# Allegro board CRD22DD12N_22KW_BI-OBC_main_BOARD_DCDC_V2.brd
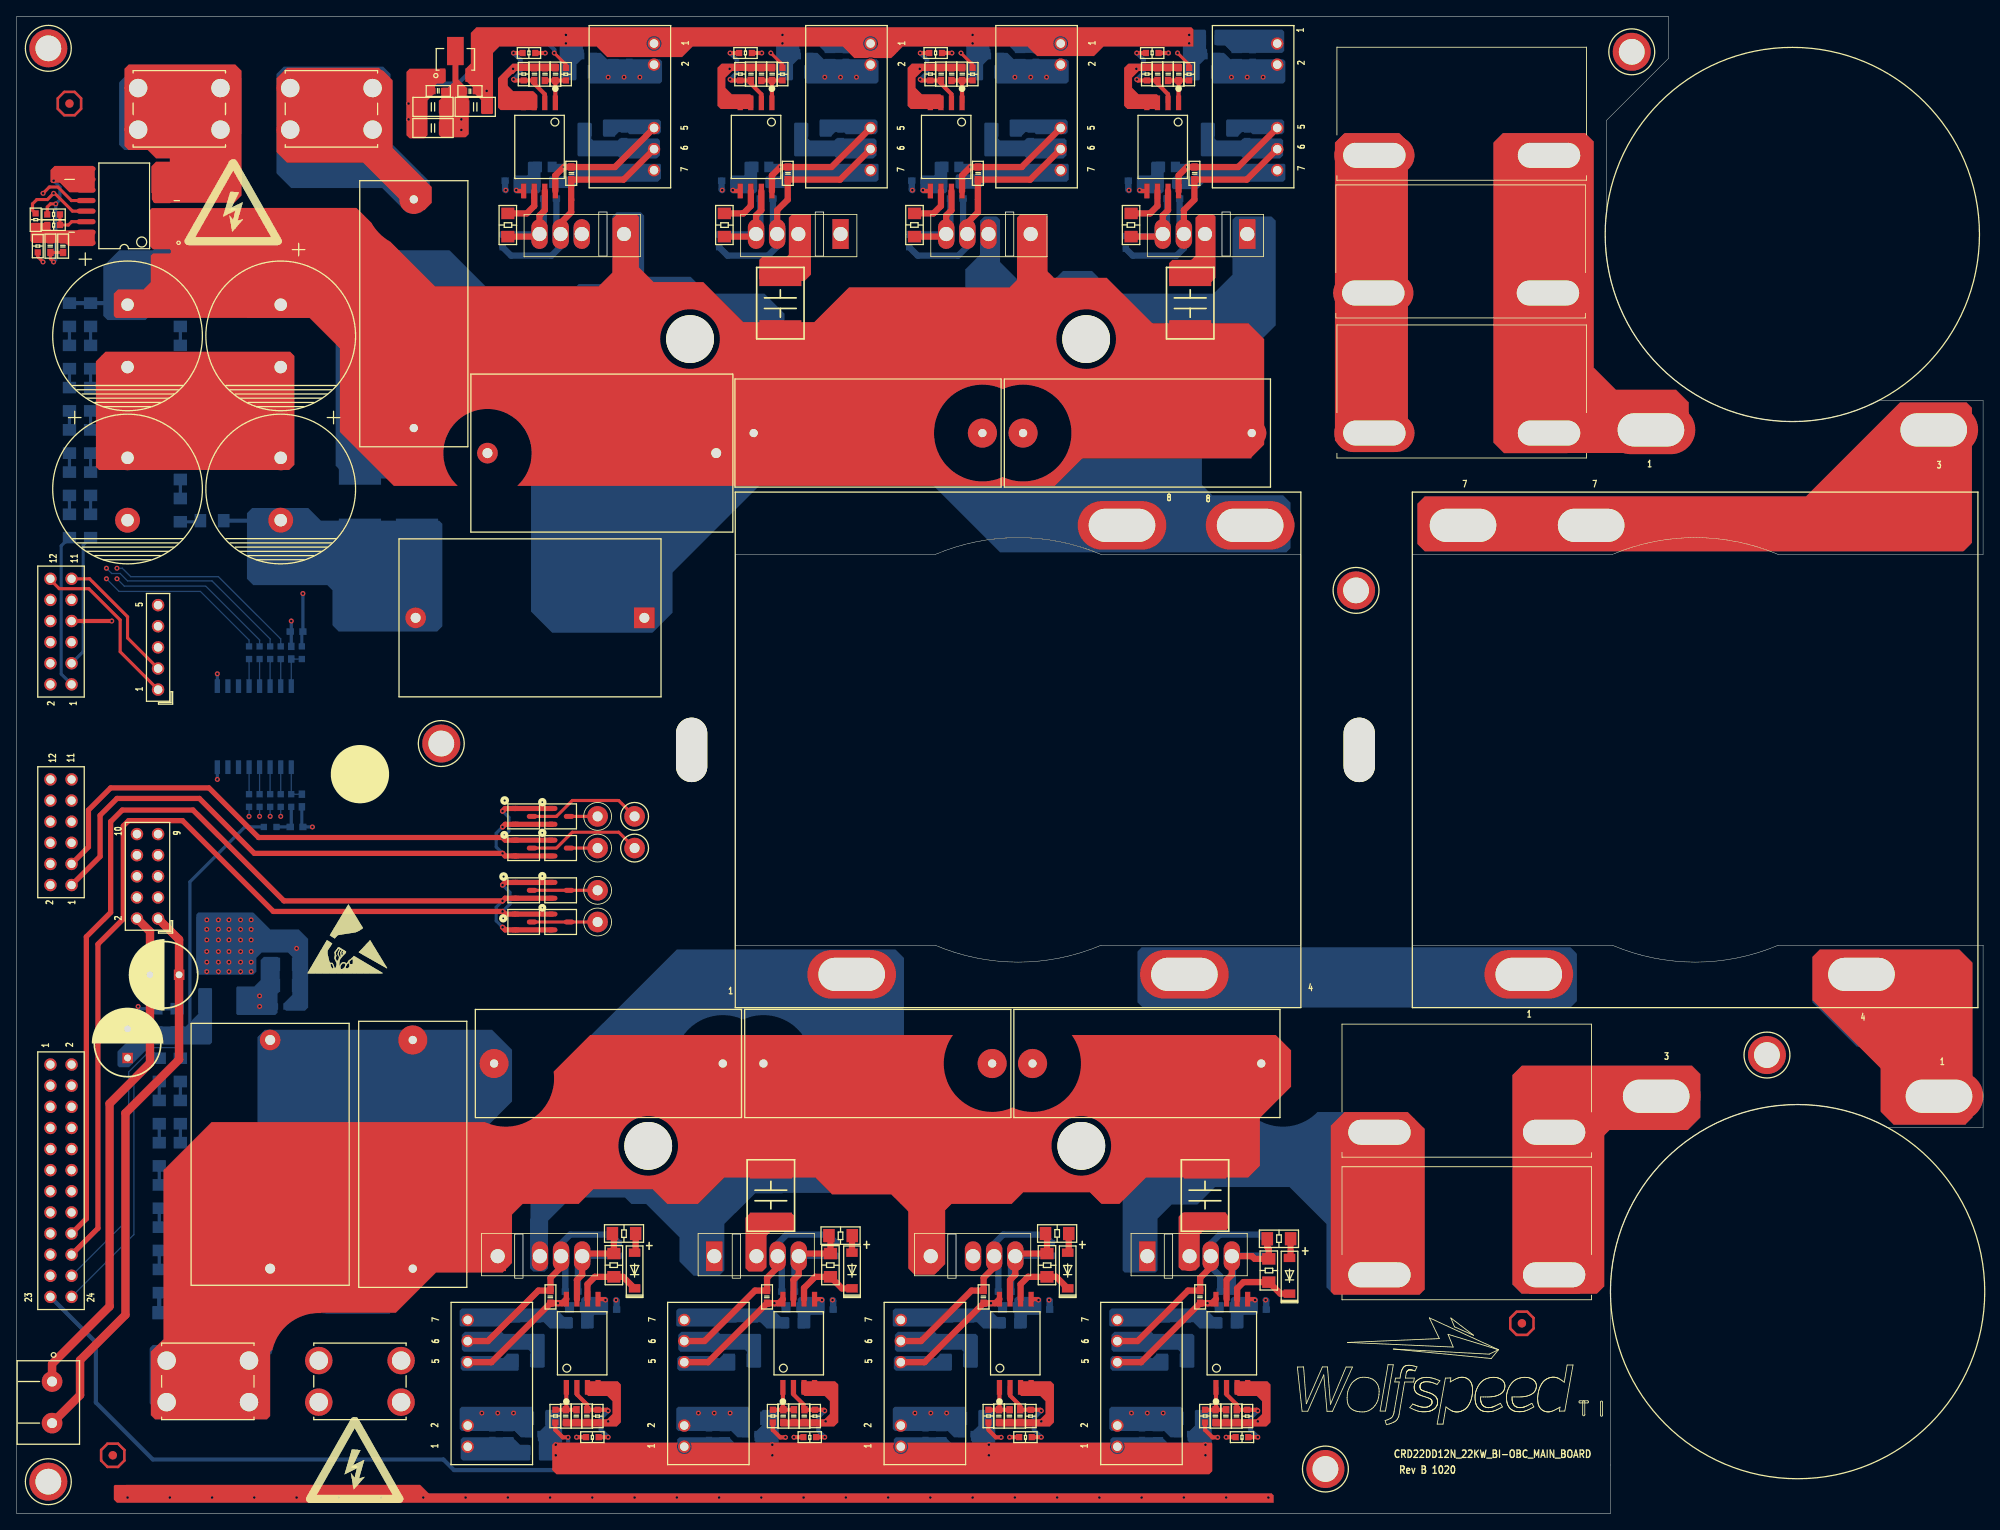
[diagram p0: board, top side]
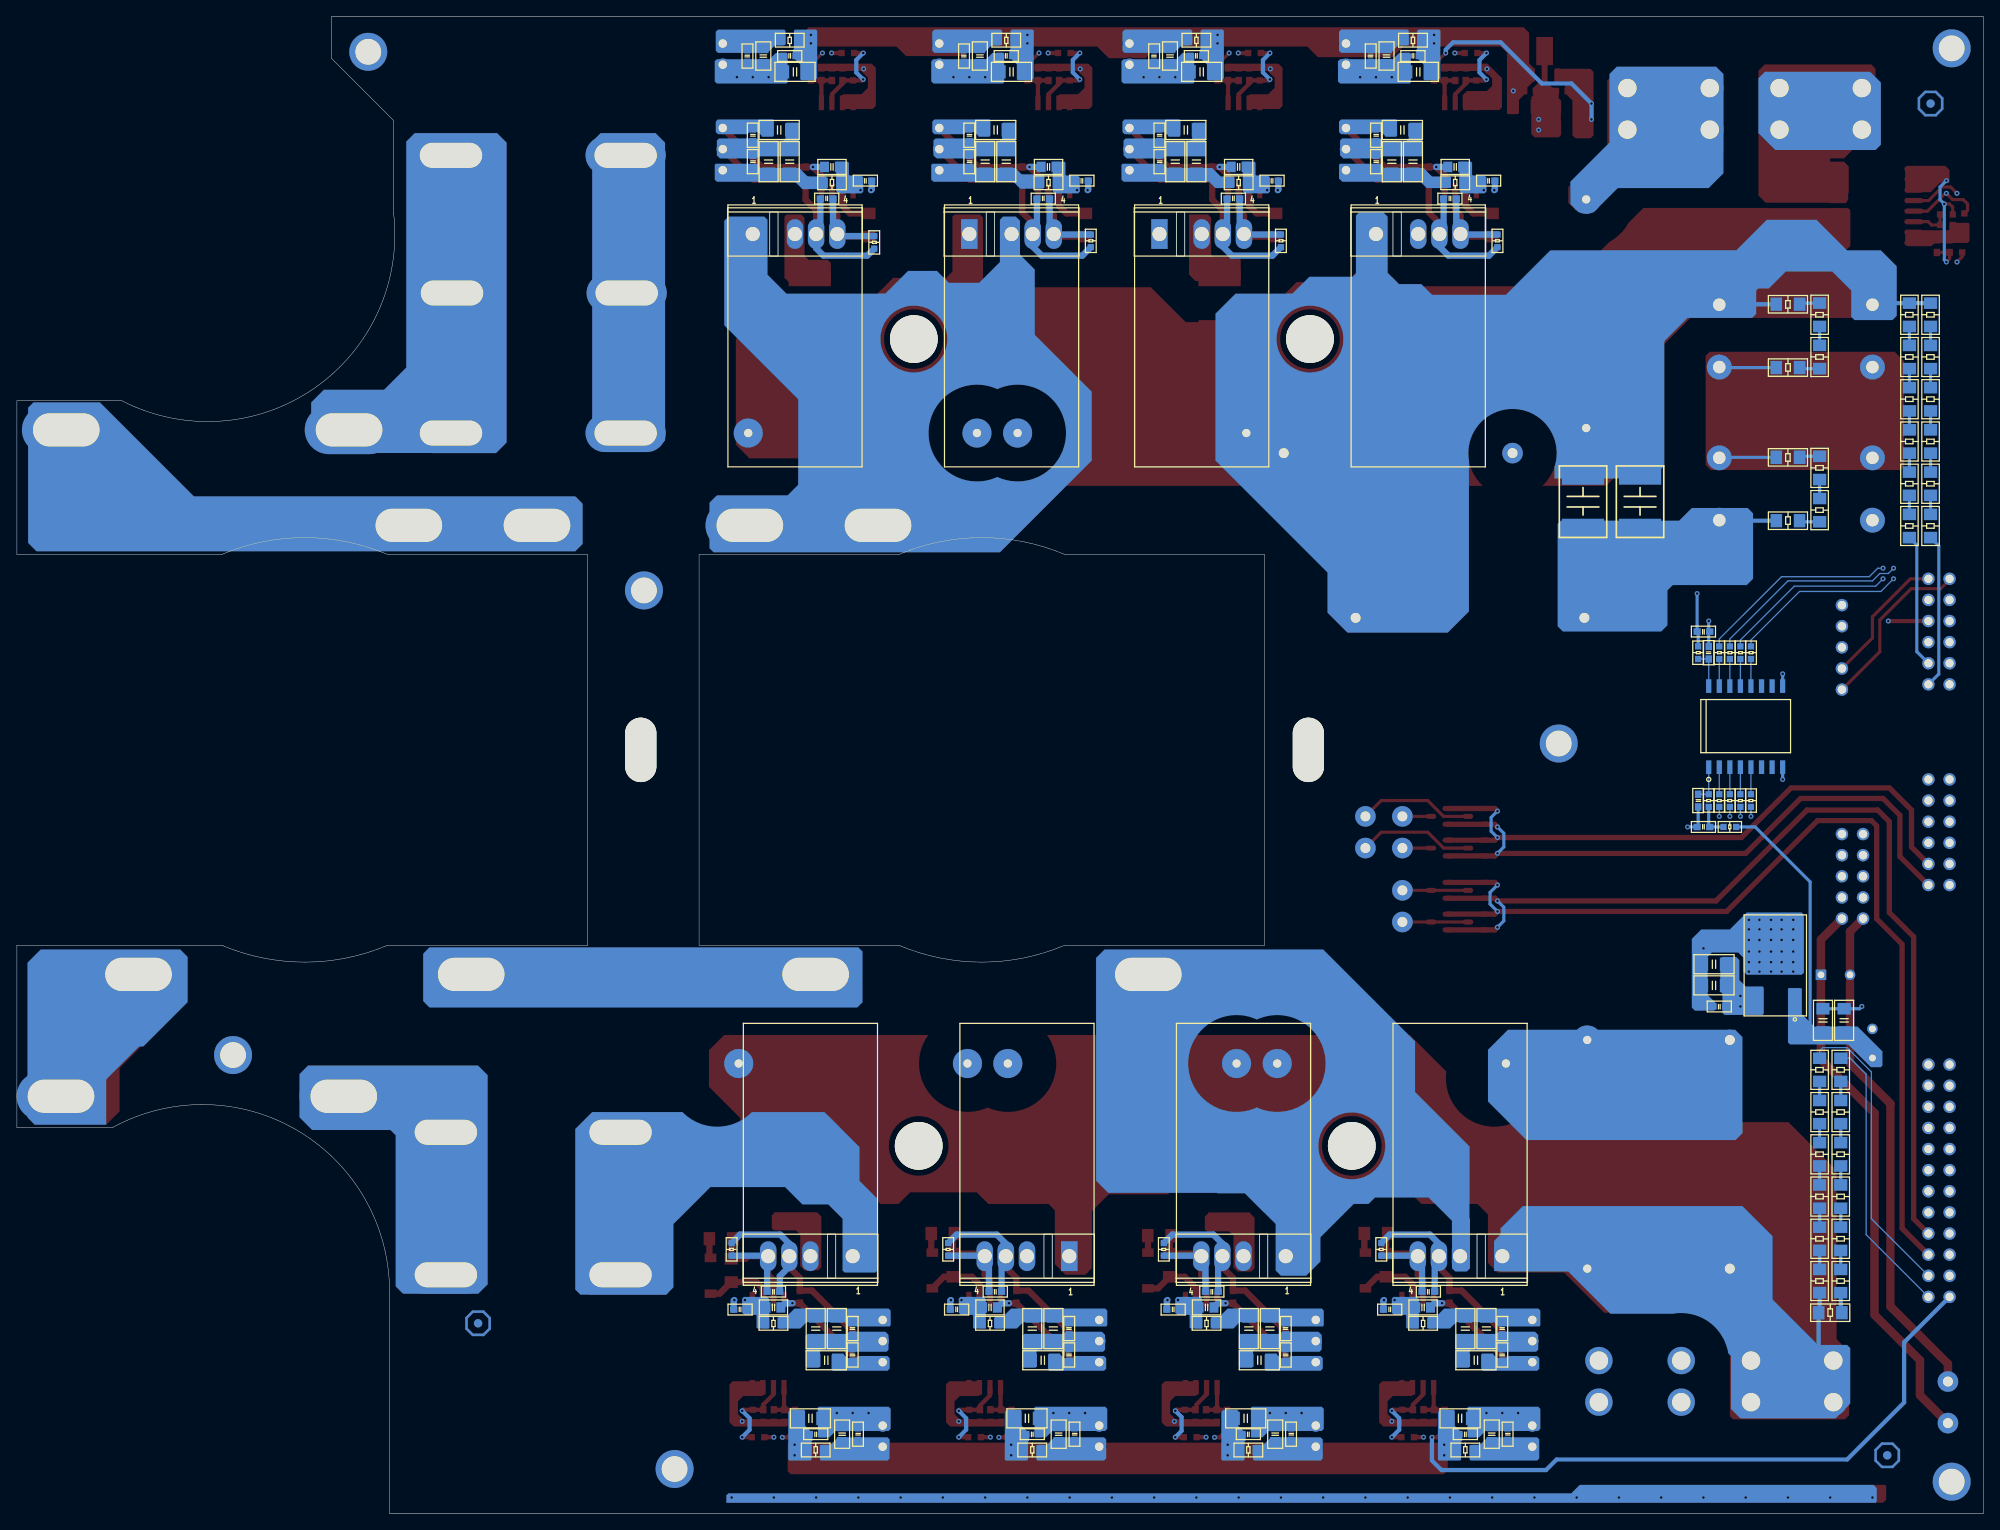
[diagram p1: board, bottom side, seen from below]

Outline 236.43 x 180 mm; copper layers: TOP, GND02, POWER03, BOTTOM. Coordinates in mm from the lower left corner of the outline.
Outline path: rectangle 59.88,28.28 60.88,33.58 ; rectangle 70.98,156.51 69.99,151.21 ; rectangle 86.04,28.28 87.04,33.58 ; rectangle 97.02,156.51 96.02,151.21 ; rectangle 111.95,28.28 112.95,33.58 ; rectangle 119.88,156.51 118.88,151.21 ; rectangle 137.98,28.28 138.98,33.58 ; rectangle 145.91,156.51 144.92,151.21 ; 0,180 198.63,180 198.63,175.01 191.13,167.51 191.13,156.38 arc(200.7,135.29) 223.8,133.81 236.43,133.81 236.43,115.32 211.8,115.32 arc(201.82,117.35) 191.84,115.32 167.79,115.32 167.79,68.33 191.84,68.33 arc(201.82,66.29) 211.8,68.33 236.43,68.33 236.43,46.39 224.94,46.39 arc(202.55,45.96) 191.62,26.41 191.62,0 0,0 0,180 ; 86.41,115.32 110.43,115.32 arc(120.41,117.35) 130.39,115.32 154.41,115.32 154.41,68.33 130.39,68.33 arc(120.41,66.29) 110.43,68.33 86.41,68.33 86.41,115.32

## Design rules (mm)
net group BUS_GAO: nets DCINPUT VO+
net group BUS_DI: nets AGND N16148550 PGND SGND SPGND
net group BUS_POWER: nets -3V_PSW5 -3V_PSW6 -3V_PSW7 -3V_PSW8 -3V_PSW9 -3V_PSW10 -3V_PSW11 -3V_PSW12 CAN5V_GND CAN_5V P6.5V VO1+ VO2+ VP+5V VP+15V VP+15V_DCDCA VP+15V_DCDCB VP+15V_DCDCC VP+15V_DCDCD VS+5V VS+15V VS+15V_DCDCA VS+15V_DCDCB VS+15V_DCDCC VS+15V_DCDCD
net group GAO: nets LEGA LEGB N17988090 N17988199 N17988317 N18067595 SLEGB

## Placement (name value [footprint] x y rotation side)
C1  0u1  [C2220]  142.88 38.23 270 top
C2  0u1  [C2220]  90.68 38.23 270 top
C4  1n  [C0603]  118.8 26.67 180 bottom
C5  1n  [C0603]  66.73 26.67 180 bottom
C7  2.2u  [CAPFILM_31_5X12_5MM]  103.53 54.1 0 top
C8  2.2u  [CAPFILM_31_5X12_5MM]  135.89 54.1 180 top
C10  2.2u  [CAPFILM_31_5X12_5MM]  71.15 54.1 180 top
C14  1n  [C0603]  92.76 26.67 180 bottom
C15  1n  [C0603]  145.47 26.67 180 bottom
C20  0.1U  [C0603]  5.59 152.4 270 top
C21  1U  [C0603]  4.06 152.4 270 top
C22  1n  [C0603]  64.14 158.12 0 bottom
C23  1n  [C0603]  113.03 158.12 0 bottom
C25  450V 180uF  [ECAP_D18P7_5]  31.75 141.6 180 top
C26  450V 180uF  [ECAP_D18P7_5]  13.34 141.6 180 top
C27  0u1  [C2220]  48.13 121.67 270 bottom
C28  0u1  [C2220]  41.27 121.67 270 bottom
C32  2.2u  [CAPFILM_31_5X12_5MM]  47.75 144.27 90 top
C33  2.2u  [CAPFILM_31_5X12_5MM]  134.75 129.92 180 top
C34  2.2u  [CAPFILM_31_5X12_5MM]  102.36 129.92 0 top
C35  5u  [CAPFILM_31_5X18_5MM]  70.36 127.51 180 top
C36  0u1  [C2220]  141.1 145.54 90 top
C37  0u1  [C2220]  91.82 145.54 90 top
C39  450V 180uF  [ECAP_D18P7_5]  31.75 123.19 180 top
C40  450V 180uF  [ECAP_D18P7_5]  13.34 123.19 180 top
C42  1n  [C0603]  90.17 158.12 0 bottom
C43  1n  [C0603]  139.06 158.12 0 bottom
C44  10u  [C1206]  55.14 169.14 0 top
C45  1U  [C0603]  54.5 171.05 0 top
C46  1U  [C0603]  50.69 171.05 180 top
C47  22u  [C1206]  50.06 169.14 180 top
C48  22u  [C1206]  50.06 166.6 180 top
C49  10u  [C1206]  32.38 63.5 180 bottom
C50  1U  [C0603]  31.75 60.96 180 bottom
C51  10u  [C1206]  32.38 66.04 180 bottom
C52  10u  [C1206]  19.28 59.29 270 bottom
C53  10u  [C1206]  16.74 59.29 270 bottom
C54  25V 220uF  [ECAP_D8P3_5]  13.34 56.52 90 top
C55  25V 220uF  [ECAP_D8P3_5]  17.78 64.77 180 top
C56  1uF  [C0603]  57.84 22.23 270 bottom
C57  4u7  [C1206]  62.28 22.23 270 bottom
C58  10uF  [C1206]  59.74 22.23 270 bottom
C59  1uF  [C0603]  83.87 22.23 270 bottom
C60  10uF  [C1206]  85.78 22.23 270 bottom
C61  4u7  [C1206]  114.35 22.23 270 bottom
C62  10uF  [C1206]  111.81 22.23 270 bottom
C64  1uF  [C0603]  135.94 22.23 270 bottom
C65  10uF  [C1206]  137.85 22.23 270 bottom
C66  10uF  [C1206]  62.92 11.43 180 bottom
C67  1uF  [C0603]  62.28 9.53 180 bottom
C68  4u7  [C1206]  88.32 22.23 270 bottom
C69  1uF  [C0603]  109.91 22.23 270 bottom
C70  1uF  [C0603]  88.37 9.53 180 bottom
C71  2u2  [C0805]  85.14 9.53 90 bottom
C72  4u7  [C1206]  140.39 22.23 270 bottom
C73  0u1  [C0603]  57.2 9.53 90 bottom
C74  2u2  [C0805]  59.11 9.53 90 bottom
C75  0u1  [C0603]  83.24 9.53 90 bottom
C76  10uF  [C1206]  114.99 11.43 180 bottom
C77  1uF  [C0603]  114.35 9.53 180 bottom
C78  0u1  [C0603]  109.27 9.53 90 bottom
C79  2u2  [C0805]  111.18 9.53 90 bottom
C80  10uF  [C1206]  141.02 11.43 180 bottom
C81  10uF  [C1206]  88.69 11.43 180 bottom
C82  1uF  [C0603]  140.39 9.53 180 bottom
C83  0u1  [C0603]  135.31 9.53 90 bottom
C84  2u2  [C0805]  137.21 9.53 90 bottom
C85  1uF  [C0603]  57.84 19.05 270 bottom
C86  10uF  [C1206]  61.01 18.41 180 bottom
C87  1uF  [C0603]  109.91 19.05 270 bottom
C88  10uF  [C1206]  113.08 18.41 180 bottom
C89  1uF  [C0603]  83.87 19.05 270 bottom
C90  1uF  [C0603]  135.94 19.05 270 bottom
C91  10uF  [C1206]  87.05 18.41 180 bottom
C92  10uF  [C1206]  139.12 18.41 180 bottom
C93  1uF  [C0603]  73.03 162.56 90 bottom
C94  4u7  [C1206]  68.58 162.56 90 bottom
C95  10uF  [C1206]  71.12 162.56 90 bottom
C96  1uF  [C0603]  68.58 175.26 0 bottom
C97  1uF  [C0603]  99.06 162.56 90 bottom
C98  0u1  [C0603]  73.66 175.26 270 bottom
C99  4u7  [C1206]  94.61 162.56 90 bottom
C100  1uF  [C0603]  121.92 162.56 90 bottom
C101  10uF  [C1206]  67.94 173.35 0 bottom
C102  10uF  [C1206]  97.16 162.56 90 bottom
C103  2u2  [C0805]  71.75 175.26 270 bottom
C104  4u7  [C1206]  117.47 162.56 90 bottom
C105  10uF  [C1206]  120.02 162.56 90 bottom
C106  1uF  [C0603]  147.96 162.56 90 bottom
C107  10uF  [C1206]  146.05 162.56 90 bottom
C108  10uF  [C1206]  93.98 173.35 0 bottom
C109  0u1  [C0603]  99.69 175.26 270 bottom
C110  2u2  [C0805]  97.79 175.26 270 bottom
C111  10uF  [C1206]  116.84 173.35 0 bottom
C112  1uF  [C0603]  117.47 175.26 0 bottom
C113  1uF  [C0603]  73.03 165.74 90 bottom
C114  10uF  [C1206]  69.85 166.37 0 bottom
C115  0u1  [C0603]  122.56 175.26 270 bottom
C116  2u2  [C0805]  120.65 175.26 270 bottom
C117  4u7  [C1206]  143.51 162.56 90 bottom
C118  1uF  [C0603]  94.61 175.26 0 bottom
C119  10uF  [C1206]  142.88 173.35 0 bottom
C120  1uF  [C0603]  143.51 175.26 0 bottom
C121  0u1  [C0603]  148.59 175.26 270 bottom
C122  2u2  [C0805]  146.69 175.26 270 bottom
C123  1uF  [C0603]  99.06 165.74 90 bottom
C124  10uF  [C1206]  95.89 166.37 0 bottom
C125  1uF  [C0603]  121.92 165.74 90 bottom
C126  10uF  [C1206]  118.75 166.37 0 bottom
C127  1uF  [C0603]  147.96 165.74 90 bottom
C128  10uF  [C1206]  144.78 166.37 0 bottom
C129  0u1  [C0603]  33.66 106.05 180 bottom
C130  0u1  [C0603]  33.66 82.55 0 bottom
C131  0u1  [C0603]  34.29 85.72 90 bottom
C132  0u1  [C0603]  33.02 103.5 270 bottom
C134  1U  [C0603]  67.31 11.7 270 top
C135  0.1U  [C0603]  66.04 11.7 270 top
C136  1n  [C0603]  68.58 11.7 270 top
C137  2.2u  [C0805]  67.36 24.77 180 bottom
C138  1U  [C0603]  71.37 24.51 0 bottom
C139  1U  [C0603]  64.19 26.04 270 top
C141  1U  [C0603]  92.18 11.7 270 top
C142  0.1U  [C0603]  93.45 11.7 270 top
C143  1n  [C0603]  94.72 11.7 270 top
C144  1U  [C0603]  97.41 24.51 0 bottom
C145  2.2u  [C0805]  93.4 24.77 180 bottom
C146  1U  [C0603]  90.22 26.04 270 top
C148  1U  [C0603]  119.38 11.7 270 top
C149  0.1U  [C0603]  118.11 11.7 270 top
C150  1n  [C0603]  120.65 11.7 270 top
C151  2.2u  [C0805]  119.43 24.77 180 bottom
C152  1U  [C0603]  123.44 24.51 0 bottom
C153  1U  [C0603]  116.26 26.04 270 top
C155  1U  [C0603]  145.41 11.7 270 top
C156  0.1U  [C0603]  144.15 11.7 270 top
C157  1n  [C0603]  146.69 11.7 270 top
C158  1U  [C0603]  149.48 24.51 0 bottom
C159  2.2u  [C0805]  145.47 24.77 180 bottom
C160  1U  [C0603]  142.29 26.04 270 top
C161  1U  [C0603]  63.5 173.08 90 top
C162  0.1U  [C0603]  64.77 173.08 90 top
C163  1n  [C0603]  62.23 173.08 90 top
C164  2.2u  [C0805]  63.5 161.93 0 bottom
C165  1U  [C0603]  59.49 160.27 180 bottom
C166  1U  [C0603]  66.67 161.15 90 top
C167  1U  [C0603]  90.81 173.08 90 top
C168  0.1U  [C0603]  89.53 173.08 90 top
C169  1n  [C0603]  88.27 173.08 90 top
C170  1U  [C0603]  85.52 160.27 180 bottom
C171  2.2u  [C0805]  89.53 161.93 0 bottom
C172  1U  [C0603]  92.71 161.15 90 top
C173  0.1U  [C0603]  113.67 173.08 90 top
C174  1U  [C0603]  112.39 173.08 90 top
C175  1n  [C0603]  111.12 173.08 90 top
C176  2.2u  [C0805]  112.39 161.93 0 bottom
C177  1U  [C0603]  108.38 160.27 180 bottom
C178  1U  [C0603]  115.57 161.15 90 top
C179  1U  [C0603]  138.43 173.08 90 top
C180  0.1U  [C0603]  139.7 173.08 90 top
C181  1n  [C0603]  137.16 173.08 90 top
C182  1U  [C0603]  134.42 160.27 180 bottom
C183  2.2u  [C0805]  138.43 161.93 0 bottom
C184  1U  [C0603]  141.6 161.15 90 top
C185  2.2u  [CAPFILM_31_5X12_5MM]  47.62 43.18 90 top
C186  5u  [CAPFILM_31_5X18_5MM]  61.72 107.7 180 top
C633  5u  [CAPFILM_31_5X18_5MM]  30.48 43.18 90 top
CON1  Connecter  [THREAD4_9P9X5_1110X920]  22.99 15.88 180 top
CON2  Connecter  [THREAD4_9P9X5_1110X920]  41.27 15.88 180 top
CON3  Connecter  [THREAD4_9P9X5_1110X920]  19.56 168.91 180 top
CON4  Connecter  [THREAD4_9P9X5_1110X920]  37.85 168.91 180 top
CR1  3PIN  [CRB]  174.35 45.84 180 top
CR2  3PIN  [CRB]  174.35 28.69 180 top
CR3  3PIN  [CRB]  173.74 163.32 180 top
CR4  3PIN  [CRB]  173.61 146.77 180 top
CR5  3PIN  [CRB]  173.74 129.92 180 top
CT1  T1T2  [TH47_CR98]  69.85 74.93 270 top
CT2  T1T2  [TH47_CR98]  69.85 83.82 270 top
CT5  T1T2  [TH47_CR98]  69.85 71.12 270 top
CT6  T1T2  [TH47_CR98]  69.85 80.01 270 top
CT7  T1T2  [TH47_CR98]  74.3 83.82 0 top
CT8  T1T2  [TH47_CR98]  74.3 80.01 0 top
D1  SL14PL-TP  [SOD-123]  74.3 29.21 270 top
D2  SL14PL-TP  [SOD-123]  126.36 29.21 270 top
D3  BAT754S  [SOT-23]  60.96 74.93 270 top
D4  BAT754S  [SOT-23]  60.96 83.82 270 top
D5  BAT754S  [SOT-23]  60.96 71.12 270 top
D6  BAT754S  [SOT-23]  60.96 80.01 270 top
D7  SL14PL-TP  [SOD-123]  100.44 29.21 270 top
D8  SL14PL-TP  [SOD-123]  153.03 28.57 270 top
D9  BAT754S  [SOT-23]  65.41 71.12 270 top
D10  BAT754S  [SOT-23]  65.41 74.93 270 top
D11  BAT754S  [SOT-23]  65.41 80.01 270 top
D12  BAT754S  [SOT-23]  65.41 83.82 270 top
J1  CON24A  [CON_2MM54_12X2]  5.33 40.01 270 top
J2  CON12A  [CON_2MM54_6X2]  5.33 81.92 90 top
J3  CON12A  [CON_2MM54_6X2]  5.33 106.05 90 top
J4  CON2  [CON_5MM_2X1]  4.26 13.36 270 top
J5  CON10A  [CON_2MM54_5X2]  15.74 76.61 90 top
J6  CON5  [CON_2MM54_5X1]  17.01 104.15 90 top
L1  8u  [L6]  213.49 130.3 0 top
L2  8u  [L6]  214.12 50.16 180 top
NOREF  #VAL  [unnamed]  6.35 169.54 0 top
NOREF#2  -  [#2]  7.81 0 90 top
NOREF#3  -  [#2]  26.02 156.81 0 top
NOREF#4  -  [#2]  39.87 68.17 0 top
NOREF#5  -  [#2]  157.21 78.05 0 top
NOREF#6  -  [#2]  0 9.42 0 top
NOREF#7  #VAL  [unnamed]  161.04 111 270 top
NOREF#8  #VAL  [unnamed]  180.97 22.86 0 top
NOREF#9  #VAL  [unnamed]  194.18 175.77 270 top
NOREF#10  -  [#2]  41.27 88.9 0 top
NOREF#11  #VAL  [unnamed]  11.56 6.99 0 top
NOREF#12  #VAL  [unnamed]  51.05 92.58 270 top
NOREF#13  -  [#2]  40.63 5.55 0 top
NOREF#14  #VAL  [unnamed]  157.35 5.33 270 top
NOREF#15  #VAL  [unnamed]  3.81 3.81 270 top
NOREF#16  #VAL  [unnamed#3]  81.15 91.82 0 top
NOREF#17  #VAL  [unnamed]  3.81 176.19 270 top
NOREF#18  #VAL  [unnamed#3]  161.42 91.82 0 top
NOREF#19  #VAL  [unnamed]  210.44 55.12 270 top
NOREF#20  #VAL  [unnamed#3]  75.93 44.2 180 bottom
NOREF#21  #VAL  [unnamed]  180.97 22.86 180 bottom
NOREF#22  #VAL  [unnamed]  6.35 169.54 180 bottom
NOREF#23  #VAL  [unnamed#3]  128 44.2 180 bottom
NOREF#24  #VAL  [unnamed#3]  128.59 141.22 180 bottom
NOREF#25  #VAL  [unnamed#3]  80.96 141.22 180 bottom
NOREF#26  #VAL  [unnamed]  11.56 6.99 180 bottom
Q1  C3M0021120K  [TO-247-4L]  62.92 30.93 0 bottom
Q2  C3M0021120K  [TO-247-4L]  114.99 30.93 0 bottom
Q3  C3M0021120K  [TO-247-4L]  88.95 30.93 0 bottom
Q4  C3M0021120K  [TO-247-4L]  141.02 30.93 0 bottom
Q7  C3M0032120K  [TO-247-4L]  67.94 153.86 180 bottom
Q16  C3M0032120K  [TO-247-4L]  116.84 153.86 180 bottom
Q17  C3M0032120K  [TO-247-4L]  93.98 153.86 180 bottom
Q18  C3M0032120K  [TO-247-4L]  142.88 153.86 180 bottom
R1  4.3R  [R1206]  125.09 33.66 180 top
R2  4.3R  [R1206]  73.03 33.66 0 top
R4  10R  [R1206]  71.81 29.84 270 top
R5  10R  [R1206]  123.88 29.84 90 top
R8  10k  [R0603]  72.39 31.75 270 bottom
R9  10k  [R0603]  124.46 31.75 270 bottom
R14  4.3R  [R1206]  151.76 33.02 180 top
R15  4.3R  [R1206]  99.06 33.4 0 top
R19  10R  [R1206]  97.84 29.84 270 top
R20  10R  [R1206]  150.55 29.21 90 top
R21  10k  [R0603]  98.53 31.75 270 bottom
R22  10k  [R0603]  150.5 31.75 270 bottom
R34  0R  [R1206]  18.41 24.13 0 bottom
R36  620k  [R1206]  6.35 144.15 270 bottom
R37  620k  [R1206]  8.89 144.15 270 bottom
R38  10R  [R0603]  2.54 152.4 90 top
R39  6.8k  [R0603]  4.45 154.94 0 top
R40  10k  [R0603]  2.29 155.57 90 top
R41  620K  [R1206]  17.14 27.94 270 bottom
R42  620K  [R1206]  19.68 27.94 270 bottom
R43  620k  [R1206]  6.35 139.06 270 bottom
R44  620k  [R1206]  8.89 139.06 270 bottom
R45  1.8k  [R0603]  4.45 156.21 180 top
R46  620K  [R1206]  17.14 33.02 270 bottom
R47  620K  [R1206]  19.68 33.02 270 bottom
R48  620k  [R1206]  6.35 133.99 270 bottom
R49  620k  [R1206]  8.89 133.99 270 bottom
R50  620K  [R1206]  17.14 38.1 270 bottom
R51  620K  [R1206]  19.68 38.1 270 bottom
R52  620k  [R1206]  6.35 128.91 270 bottom
R53  620k  [R1206]  8.89 128.91 270 bottom
R54  620K  [R1206]  17.14 43.18 270 bottom
R55  620K  [R1206]  19.68 43.18 270 bottom
R56  620k  [R1206]  6.35 123.83 270 bottom
R57  620k  [R1206]  8.89 123.83 270 bottom
R58  10R  [R1206]  59.05 154.94 90 top
R59  10R  [R1206]  107.95 154.94 270 top
R60  620K  [R1206]  17.14 48.26 270 bottom
R61  620K  [R1206]  19.68 48.26 270 bottom
R62  10k  [R0603]  58.42 153.03 90 bottom
R63  510k  [R1206]  23.5 145.41 180 bottom
R64  10k  [R0603]  107.31 153.03 90 bottom
R65  620k  [R1206]  6.35 118.75 270 bottom
R66  620k  [R1206]  8.89 118.75 270 bottom
R67  510k  [R1206]  19.68 144.15 270 bottom
R68  510k  [R1206]  19.68 139.06 270 bottom
R69  620K  [R1206]  17.14 53.34 270 bottom
R70  620K  [R1206]  19.68 53.34 270 bottom
R71  510k  [R1206]  23.5 137.79 0 bottom
R72  9R1  [R1206]  85.09 154.94 90 top
R73  9R1  [R1206]  133.99 154.94 270 top
R74  510k  [R1206]  23.5 127 180 bottom
R75  10k  [R0603]  84.45 153.03 90 bottom
R76  10k  [R0603]  133.35 152.85 90 bottom
R77  510k  [R1206]  19.68 125.73 270 bottom
R78  510k  [R1206]  19.68 120.65 270 bottom
R79  510k  [R1206]  23.5 119.38 0 bottom
R84  1R  [R0805]  62.28 7.62 0 bottom
R85  1R  [R0805]  88.37 7.62 0 bottom
R86  1R  [R0805]  114.35 7.62 0 bottom
R87  1R  [R0805]  140.39 7.62 0 bottom
R88  1R  [R0805]  68.58 177.16 180 bottom
R89  1R  [R0805]  94.61 177.16 180 bottom
R90  1R  [R0805]  117.47 177.16 180 bottom
R91  1R  [R0805]  143.51 177.16 180 bottom
R92  10R  [R0603]  30.48 82.55 0 bottom
R93  10R  [R0603]  34.29 103.5 90 bottom
R94  10R  [R0603]  33.02 85.72 270 bottom
R95  51R  [R0603]  31.75 85.72 270 bottom
R96  51R  [R0603]  31.75 103.5 90 bottom
R97  51R  [R0603]  30.48 85.72 270 bottom
R98  51R  [R0603]  30.48 103.5 90 bottom
R99  51R  [R0603]  29.21 85.72 270 bottom
R100  51R  [R0603]  29.21 103.5 90 bottom
R101  51R  [R0603]  27.94 85.72 270 bottom
R102  51R  [R0603]  27.94 103.5 90 bottom
R103  10R  [R0603]  64.77 11.7 90 top
R104  100  [R0603]  69.22 9.16 0 top
R105  4.7K  [R0603]  69.85 11.7 270 top
R106  1R  [R0805]  67.36 22.86 180 bottom
R107  10R  [R0603]  90.91 11.7 90 top
R108  100  [R0603]  95.36 9.16 0 top
R109  1R  [R0805]  93.4 22.86 180 bottom
R110  4.7K  [R0603]  95.99 11.7 270 top
R111  10R  [R0603]  116.84 11.7 90 top
R112  100  [R0603]  121.28 9.16 0 top
R113  1R  [R0805]  119.43 22.86 180 bottom
R114  4.7K  [R0603]  121.92 11.7 270 top
R115  10R  [R0603]  142.88 11.7 90 top
R116  100  [R0603]  147.32 9.16 0 top
R117  4.7K  [R0603]  147.96 11.7 270 top
R118  1R  [R0805]  145.47 22.86 180 bottom
R119  10R  [R0603]  66.04 173.08 270 top
R120  100  [R0603]  61.59 175.62 180 top
R121  1R  [R0805]  63.5 160.02 0 bottom
R122  4.7K  [R0603]  60.96 173.08 90 top
R123  10R  [R0603]  92.08 173.08 270 top
R124  100  [R0603]  87.63 175.62 180 top
R125  4.7K  [R0603]  87 173.08 90 top
R126  1R  [R0805]  89.53 160.02 0 bottom
R127  10R  [R0603]  114.94 173.08 270 top
R128  100  [R0603]  110.49 175.62 180 top
R129  1R  [R0805]  112.39 160.02 0 bottom
R130  4.7K  [R0603]  109.86 173.08 90 top
R131  10R  [R0603]  140.97 173.08 270 top
R132  100  [R0603]  136.53 175.62 180 top
R133  4.7K  [R0603]  135.89 173.08 90 top
R134  1R  [R0805]  138.43 160.02 0 bottom
T1  50uH  [XFMR-PQ6562_T1]  201.8 91.82 180 top
T2  50uH  [XFMR-PQ6562_T2]  120.4 91.82 180 top
U1  ACS733  [SOICW-16]  12.93 157.25 180 top
U2  MC78L05F-TP  [SOT-89-3L]  52.75 174.41 90 top
U3  LF50ABDT-TR  [TO252AB]  24.96 68.83 180 bottom
U4  R15P21503D  [G1212S_2W11]  56.33 15.64 90 top
U5  R15P21503D  [G1212S_2W11]  82.37 15.64 90 top
U6  R15P21503D  [G1212S_2W11]  134.44 15.64 90 top
U7  R15P21503D  [G1212S_2W11]  108.4 15.64 90 top
U8  R15P21503D  [G1212S_2W11]  74.53 169.14 270 top
U9  R15P21503D  [G1212S_2W11]  100.56 169.14 270 top
U10  R15P21503D  [G1212S_2W11]  123.42 169.14 270 top
U11  R15P21503D  [G1212S_2W11]  149.46 169.14 270 top
U12  Si8662  [WB_SOIC16]  28.57 94.61 180 bottom
U13  UCC5350MC  [SOIC8_DWV]  68 20.46 90 top
U14  UCC5350MC  [SOIC8_DWV]  94.03 20.46 90 top
U15  UCC5350MC  [SOIC8_DWV]  120.07 20.46 90 top
U16  UCC5350MC  [SOIC8_DWV]  146.1 20.46 90 top
U17  UCC5350MC  [SOIC8_DWV]  62.87 164.33 270 top
U18  UCC5350MC  [SOIC8_DWV]  88.9 164.33 270 top
U19  UCC5350MC  [SOIC8_DWV]  111.76 164.33 270 top
U20  UCC5350MC  [SOIC8_DWV]  137.79 164.33 270 top

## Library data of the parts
C1 C2 C27 C28 C36 C37 = CAP NP
C4 C5 C7 C8 C10 C14 C15 C20-C23 C32-C34 C42-C53 C56-C62 C64-C132 C134-C139 C141-C146 C148-C153 C155-C185 = CAP NP: User Part Number: HAMP; Tolerance: #TOL
C25 C26 C39 C40 C54 C55 = CAP POL: User Part Number: HAMP; Tolerance: #TOL
C35 C186 C633 = CAP NP: Tolerance: #TOL; User Part Number: HAMP
CON1-CON4 = Connecter: Tolerance: #TOL; User Part Number: HAMP
CR1-CR5 = 3PIN: Tolerance: #TOL; User Part Number: HAMP
CT1 CT2 CT5-CT8 = CON1_2: Tolerance: #TOL; User Part Number: HAMP
D1 D2 D7 D8 = DIODE_0: Tolerance: #TOL; User Part Number: HAMP
D3-D6 D9-D12 = FMMD6100/SOT_0: User Part Number: HAMP; Tolerance: #TOL
J1 = CON24A: User Part Number: HAMP; Tolerance: #TOL
J2 J3 = CON12A: User Part Number: HAMP; Tolerance: #TOL
J4 = CON2: User Part Number: HAMP; Tolerance: #TOL
J5 = CON10A: User Part Number: HAMP; Tolerance: #TOL
J6 = CON5: User Part Number: HAMP; Tolerance: #TOL
L1 = 126LNS_1: Tolerance: #TOL; User Part Number: HAMP
L2 = 126LNS_5: Tolerance: #TOL; User Part Number: HAMP
NOREF NOREF#7-NOREF#9 NOREF#11 NOREF#15 NOREF#18 NOREF#20-NOREF#22 NOREF#24 NOREF#26 = -: Tolerance: #TOL; User Part Number: HAMP
NOREF#12 NOREF#14 NOREF#16 NOREF#17 NOREF#19 NOREF#23 NOREF#25 = -: User Part Number: HAMP; Tolerance: #TOL
Q1-Q4 Q7 Q16-Q18 = C3M0065090J_4: User Part Number: HAMP; Tolerance: #TOL
R1 R2 R4 R5 R14 R15 R19 R20 R36 R37 R43 R44 R48 R49 R52 R53 R56-R59 R65 R66 R72 R73 = R: Tolerance: #TOL; User Part Number: HAMP
R8 R9 R21 R22 R38-R40 R45 R62 R64 R75 R76 R103 R106 R107 R109 R111 R113 R115 R118 R119 R121 R123 R126 R127 R129 R131 R134 = R: User Part Number: HAMP; Tolerance: #TOL
R34 R41 R42 R46 R47 R50 R51 R54 R55 R60 R61 R63 R67-R71 R74 R77-R79 = RESISTOR: Tolerance: #TOL; User Part Number: HAMP
R84-R102 R104 R105 R108 R110 R112 R114 R116 R117 R120 R122 R124 R125 R128 R130 R132 R133 = RESISTOR: User Part Number: HAMP; Tolerance: #TOL
T1 T2 = LET0234_326uH_0: User Part Number: HAMP; Tolerance: #TOL
U1 = MCR1101_0: User Part Number: HAMP; Tolerance: #TOL
U2 U3 = MC78L05F-TP: User Part Number: HAMP; Tolerance: #TOL
U4-U11 = E1212S-2WR2_3: Tolerance: #TOL; User Part Number: HAMP
U12 = Si8661_3: User Part Number: HAMP; Tolerance: #TOL
U13-U20 = UCC5350MC: Tolerance: #TOL; User Part Number: HAMP

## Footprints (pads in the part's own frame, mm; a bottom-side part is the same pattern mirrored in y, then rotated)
C0603
  rect 0.889x0.787 smd: 1(-0.76,0) 2(0.76,0)
C0805
  rect 1.092x1.27 smd: 1(-0.89,0) 2(0.89,0)
C1206
  rect 1.397x1.6 smd: 1(-1.4,0) 2(1.4,0)
C2220
  rect 1.905x5.08 smd: 1(-3,0) 2(3,0)
CAPFILM_31_5X12_5MM
  round 3.505 hole 0.991: 1(-13.75,0) 2(13.75,0)
CAPFILM_31_5X18_5MM
  rect 2.489x2.489 hole 1.194: 1(-13.75,0)
  round 2.489 hole 1.194: 2(13.75,0)
CON_2MM54_5X1
  round 1.499 hole 1.016: 1(-5.08,0) 2(-2.54,0) 3(0,0) 4(2.54,0) 5(5.08,0)
CON_2MM54_5X2
  round 1.499 hole 1.016: 1(-5.08,-1.27) 2(-5.08,1.27) 3(-2.54,-1.27) 4(-2.54,1.27) 5(0,-1.27) 6(0,1.27) 7(2.54,-1.27) 8(2.54,1.27) 9(5.08,-1.27) 10(5.08,1.27)
CON_2MM54_6X2
  round 1.499 hole 0.991: 1(-6.35,-1.27) 2(-6.35,1.27) 3(-3.81,-1.27) 4(-3.81,1.27) 5(-1.27,-1.27) 6(-1.27,1.27) 7(1.27,-1.27) 8(1.27,1.27) 9(3.81,-1.27) 10(3.81,1.27) 11(6.35,-1.27) 12(6.35,1.27)
CON_2MM54_12X2
  round 1.499 hole 0.991: 1(-13.97,-1.27) 2(-13.97,1.27) 3(-11.43,-1.27) 4(-11.43,1.27) 5(-8.89,-1.27) 6(-8.89,1.27) 7(-6.35,-1.27) 8(-6.35,1.27) 9(-3.81,-1.27) 10(-3.81,1.27) 11(-1.27,-1.27) 12(-1.27,1.27) 13(1.27,-1.27) 14(1.27,1.27) 15(3.81,-1.27) 16(3.81,1.27) 17(6.35,-1.27) 18(6.35,1.27) 19(8.89,-1.27) 20(8.89,1.27) 21(11.43,-1.27) 22(11.43,1.27) 23(13.97,-1.27) 24(13.97,1.27)
CON_5MM_2X1
  round 2.489 hole 1.194: 1(-2.5,0) 2(2.5,0)
CRB
  oval 9.652x4.572 hole 7.493x2.997: 1(-10.5,0) 2(10.5,0)
ECAP_D8P3_5
  rect 1.27x1.27 hole 0.813: 1(-1.75,0)
  round 1.27 hole 0.813: 2(1.75,0)
ECAP_D18P7_5
  round 3 hole 1.5: 1(0,-3.75) 2(0,3.75)
G1212S_2W11
  round 1.499 hole 1.016: 1(-7.62,2.1) 2(-5.08,2.1) 5(2.54,2.1) 6(5.08,2.1) 7(7.62,2.1)
L6
  oval 10.668x5.842 hole 8.001x3.988: 1(-17,0) 3(17,0)
R0603
  rect 0.762x0.762 smd: 1(-0.76,0) 2(0.76,0)
R0805
  rect 0.991x1.194 smd: 1(-1,0) 2(1,0)
R1206
  rect 1.397x1.6 smd: 1(-1.4,0) 2(1.4,0)
SOD-123
  rect 1.02x1.4 smd: 1(-2.15,0) 2(2.15,0)
SOIC8_DWV
  rect 1.778x0.635 smd: 1(-5.3,1.905) 2(-5.3,0.635) 3(-5.3,-0.635) 4(-5.3,-1.905) 5(5.3,-1.905) 6(5.3,-0.635) 7(5.3,0.635) 8(5.3,1.905)
SOICW-16
  oval 2.286x0.635 smd: 1(-4.578,4.445) 2(-4.578,3.175) 3(-4.578,1.905) 4(-4.578,0.635) 5(-4.578,-0.635) 6(-4.578,-1.905) 7(-4.578,-3.175) 8(-4.578,-4.445) 9(4.578,-4.445) 10(4.578,-3.175) 11(4.578,-1.905) 12(4.578,-0.635) 13(4.578,0.635) 14(4.578,1.905) 15(4.578,3.175) 16(4.578,4.445)
SOT-23
  oval 0.61x1.27 smd: 1(-0.95,-1.01) 2(0.95,-1.01) 3(0,1.01)
SOT-89-3L
  rect 3.404x2.007 smd: (1.45,0)
  rect 1.6x0.61 smd: 1(-1.45,1.5) 3(-1.45,-1.5)
  rect 2.007x0.711 smd: 2(-1.25,0)
TH47_CR98
  round 2.489 hole 1.194: 1(0,0)
THREAD4_9P9X5_1110X920
  round 3.302 hole 2.21: 1(4.95,2.5) 2(-4.95,2.5) 3(-4.95,-2.5) 4(4.95,-2.5)
TO252AB
  rect 1.6x2.997 smd: 1(2.3,-7.16) 3(-2.3,-7.16)
  rect 6.706x6.706 smd: 2(0,-0.51)
TO-247-4L
  rect 1.981x3.581 hole 1.702: 1(-5.08,0)
  oval 1.981x3.581 hole 1.702: 2(0,0) 3(2.54,0) 4(5.08,0)
unnamed
  round 1.016 smd: 1(0,0)
unnamed#3
  oval 3.759x7.747 hole 4.013x8.001 unplated: (0,0)
WB_SOIC16
  rect 0.635x1.651 smd: 1(-4.445,-4.877) 2(-3.175,-4.877) 3(-1.905,-4.877) 4(-0.635,-4.877) 5(0.635,-4.877) 6(1.905,-4.877) 7(3.175,-4.877) 8(4.445,-4.877) 9(4.445,4.877) 10(3.175,4.877) 11(1.905,4.877) 12(0.635,4.877) 13(-0.635,4.877) 14(-1.905,4.877) 15(-3.175,4.877) 16(-4.445,4.877)
XFMR-PQ6562_T1
  oval 10.668x5.842 hole 8.001x3.988: 1(20,27) 4(-20,27) 7(12.5,-27) 8(53.5,-27)
XFMR-PQ6562_T2
  oval 10.668x5.842 hole 8.001x3.988: 1(20,27) 4(-20,27) 7(-53.5,-27) 8(-12.5,-27)

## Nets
-3V_PSW5: C85.2 C86.2 C137.2 C139.2 U4.5(-VOUT) U13.8(VEE2)
-3V_PSW6: C89.2 C91.2 C145.2 C146.2 U5.5(-VOUT) U14.8(VEE2)
-3V_PSW7: C87.2 C88.2 C151.2 C153.2 U7.5(-VOUT) U15.8(VEE2)
-3V_PSW8: C90.2 C92.2 C159.2 C160.2 U6.5(-VOUT) U16.8(VEE2)
-3V_PSW9: C113.2 C114.2 C164.2 C166.2 U8.5(-VOUT) U17.8(VEE2)
-3V_PSW10: C123.2 C124.2 C171.2 C172.2 U9.5(-VOUT) U18.8(VEE2)
-3V_PSW11: C125.2 C126.2 C176.2 C178.2 U10.5(-VOUT) U19.8(VEE2)
-3V_PSW12: C127.2 C128.2 C183.2 C184.2 U11.5(-VOUT) U20.8(VEE2)
AGND: C20.2 C21.2 C49.1 C50.1 C51.1 C52.1 C53.1 C54.2 C66.2 C67.2 C70.2 C71.2 C73.2 C74.2 C75.2 C76.2 C77.2 C78.2 C79.2 C80.2 C81.2 C82.2 C83.2 C84.2 C130.2 C131.1 C134.2 C135.2 C136.2 C141.2 C142.2 C143.2 C148.2 C149.2 C150.2 C155.2 C156.2 C157.2 J1.13 J1.15 J1.17 J1.19 J1.21 J2.6 J2.8 J5.6 J5.9 R45.2 R105.2 R110.2 R114.2 R117.2 U1.9(GND) U1.10(GND1) U1.11(PROGRAM) U3.2(GND) U4.2(-VIN) U5.2(-VIN) U6.2(-VIN) U7.2(-VIN) U12.8(GND1) U13.3(IN-) U13.4(GND1) U14.3(IN-) U14.4(GND1) U15.3(IN-) U15.4(GND1) U16.3(IN-) U16.4(GND1)
P6.5V: C49.2 C50.2 C51.2 J5.10 U3.3(VIN)
PGND: C1.2 C2.2 C7.2 C8.2 C10.2 C185.2 C633.2 CON2.1 CON2.2 CON2.3 CON2.4 Q3.2(S) Q4.2(S)
SGND: C44.1 C45.1 C46.1 C47.1 C48.1 C96.2 C98.2 C101.2 C103.2 C108.2 C109.2 C110.2 C111.2 C112.2 C115.2 C116.2 C118.2 C119.2 C120.2 C121.2 C122.2 C129.2 C132.1 C161.2 C162.2 C163.2 C167.2 C168.2 C169.2 C173.2 C174.2 C175.2 C179.2 C180.2 C181.2 J3.5 J6.5 R122.2 R125.2 R130.2 R133.2 U2.2(GND) U8.2(-VIN) U9.2(-VIN) U10.2(-VIN) U11.2(-VIN) U12.9(GND2) U17.3(IN-) U17.4(GND1) U18.3(IN-) U18.4(GND1) U19.3(IN-) U19.4(GND1) U20.3(IN-) U20.4(GND1)
CAN5V_GND: J3.11 J6.2
CAN_5V: J3.12 J6.1
CLAMPQA: C5.1 Q1.4(G) R2.1 R4.1 R8.2 U13.7(CLAMP)
CLAMPQB: C14.1 Q3.4(G) R15.1 R19.1 R21.2 U14.7(CLAMP)
CLAMPQC: C4.1 Q2.4(G) R1.2 R5.2 R9.2 U15.7(CLAMP)
CLAMPQD: C15.1 Q4.4(G) R14.2 R20.2 R22.2 U16.7(CLAMP)
CLAMPQSA: C22.1 Q7.4(G) R58.1 R62.2 U17.7(CLAMP)
CLAMPQSB: C42.1 Q17.4(G) R72.1 R75.2 U18.7(CLAMP)
CLAMPQSC: C23.1 Q16.4(G) R59.2 R64.2 U19.7(CLAMP)
CLAMPQSD: C43.1 Q18.4(G) R73.2 R76.2 U20.7(CLAMP)
CS: D4.2(C2) D6.2(C2) D11.2(C2) D12.2(C2) J2.1
CS_PRI: D3.2(C2) D5.2(C2) D9.2(C2) D10.2(C2) J1.18
CS_RTN: D4.1(C1) D6.1(C1) D11.1(C1) D12.1(C1) J2.3
CS_RTN_PRI: D3.1(C1) D5.1(C1) D9.1(C1) D10.1(C1) J1.20
DC-OV: J1.22 R70.1
DC_14V_INPUT: C55.1 J4.2 J5.1
DC_FB: J1.24 R69.1
DCINPUT: C1.1 C2.1 C7.1 C8.1 C10.1 C185.1 C633.1 CON1.1 CON1.2 CON1.3 CON1.4 Q1.1(D) Q2.1(D) R34.2 R42.2
DCPWM1A_1H: J2.4 R104.1
DCPWM1A_1L: J2.2 R108.1
DCPWM2A_2H: J2.7 R112.1
DCPWM2A_2L: J2.5 R116.1
DRVA: D1.2(K) R4.2 U13.6(OUT)
DRVA_G: C5.2 C56.2 C57.2 C58.2 C85.1 C86.1 C138.2 C139.1 Q1.3(GS) R8.1 U4.6(COM)
DRVB: D7.2(K) R19.2 U14.6(OUT)
DRVB_G: C14.2 C59.2 C60.2 C68.2 C89.1 C91.1 C144.2 C146.1 Q3.3(GS) R21.1 U5.6(COM)
DRVC: D2.2(K) R5.1 U15.6(OUT)
DRVC_G: C4.2 C61.2 C62.2 C69.2 C87.1 C88.1 C152.2 C153.1 Q2.3(GS) R9.1 U7.6(COM)
DRVD: D8.2(K) R20.1 U16.6(OUT)
DRVD_G: C15.2 C64.2 C65.2 C72.2 C90.1 C92.1 C158.2 C160.1 Q4.3(GS) R22.1 U6.6(COM)
DRVSA: R58.2 U17.6(OUT)
DRVSB: R72.2 U18.6(OUT)
DRVSC: R59.1 U19.6(OUT)
DRVSD: R73.1 U20.6(OUT)
IGND: C55.2 J4.1 J5.2
IOUT_ADC: J1.14 U1.12(VIOUT)
LEGA: Q1.2(S) Q3.1(D) T2.1
LEGB: CR1.2 CR2.2 Q2.2(S) Q4.1(D)
OUTPUT_OC: J1.16 R40.2 U1.13(FAULT)
PWM1A: J1.1
PWM1B: J1.3
PWM1C: J1.5
PWM1D: J1.7
PWM1E: J1.9
PWM1F: J1.11
SLEGA: CR3.2 CR4.2 CR5.2 Q7.2(S) Q17.1(D)
SLEGB: Q16.2(S) Q18.1(D) T1.8 T2.8
SPGND: C27.2 C28.2 C32.2 C33.2 C34.2 C35.2 C36.2 C37.2 C39.2 C40.2 C186.2 CON4.1 CON4.2 CON4.3 CON4.4 Q17.2(S) Q18.2(S) R79.2
SR-PWM-A: J2.9 R95.2
SR-PWM-A-S: R96.2 R120.1
SR-PWM-B: J2.10 R97.2
SR-PWM-B-S: R98.2 R124.1
SR-PWM-C: J2.11 R99.2
SR-PWM-C-S: R100.2 R128.1
SR-PWM-D: J2.12 R101.2
SR-PWM-D-S: R102.2 R132.1
SRA_G: C22.2 C93.2 C94.2 C95.2 C113.1 C114.1 C165.2 C166.1 Q7.3(GS) R62.1 U8.6(COM)
SRB_G: C42.2 C97.2 C99.2 C102.2 C123.1 C124.1 C170.2 C172.1 Q17.3(GS) R75.1 U9.6(COM)
SRC_G: C23.2 C100.2 C104.2 C105.2 C125.1 C126.1 C177.2 C178.1 Q16.3(GS) R64.1 U10.6(COM)
SRD_G: C43.2 C106.2 C107.2 C117.2 C127.1 C128.1 C182.2 C184.1 Q18.3(GS) R76.1 U11.6(COM)
VO1+: J3.1 R65.2
VO2+: J3.3 R66.2
VO+: C25.1 C26.1 C27.1 C28.1 C32.1 C33.1 C34.1 C35.1 C36.1 C37.1 C186.1 Q7.1(D) Q16.1(D) R36.1 R37.1 R63.1 U1.1(IP1+) U1.2(IP2+) U1.3(IP3+) U1.4(IP4+)
VP3.3D: J1.6 R38.1
VP+5V: C52.2 C53.2 C54.1 J1.23 R92.1 R103.1 R107.1 R111.1 R115.1 U3.1(VOUT)
VP+15V: C66.1 C67.1 C70.1 C76.1 C77.1 C80.1 C81.1 C82.1 J5.5 R84.2 R85.2 R86.2 R87.2
VP+15V_DCDCA: C56.1 C57.1 C58.1 R106.2 U4.7(+VOUT)
VP+15V_DCDCB: C59.1 C60.1 C68.1 R109.2 U5.7(+VOUT)
VP+15V_DCDCC: C61.1 C62.1 C69.1 R113.2 U7.7(+VOUT)
VP+15V_DCDCD: C64.1 C65.1 C72.1 R118.2 U6.7(+VOUT)
VS+5V: C46.2 C47.2 C48.2 C129.1 J3.7 R93.2 R119.1 R123.1 R127.1 R131.1 U2.1(VOUT)
VS+15V: C44.2 C45.2 C96.1 C101.1 C108.1 C111.1 C112.1 C118.1 C119.1 C120.1 J6.4 R88.2 R89.2 R90.2 R91.2 U2.3(VIN)
VS+15V_DCDCA: C93.1 C94.1 C95.1 R121.2 U8.7(+VOUT)
VS+15V_DCDCB: C97.1 C99.1 C102.1 R126.2 U9.7(+VOUT)
VS+15V_DCDCC: C100.1 C104.1 C105.1 R129.2 U10.7(+VOUT)
VS+15V_DCDCD: C106.1 C107.1 C117.1 R134.2 U11.7(+VOUT)
N16123922: CON3.1 CON3.2 CON3.3 CON3.4 U1.5(IP1-) U1.6(IP2-) U1.7(IP3-) U1.8(IP4-)
N16148248: R63.2 R67.1
N16148534: R68.2 R71.1
N16148538: R67.2 R68.1
N16148540: R74.2 R77.1
N16148544: R78.2 R79.1
N16148550: C25.2 C26.2 C39.1 C40.1 R71.2 R74.1
N16320789: R77.2 R78.1
N17266948: R37.2 R44.1
N17266951: R44.2 R49.1
N17453412: C109.1 C110.1 R89.1 U9.1(+VIN)
N17453587: C98.1 C103.1 R88.1 U8.1(+VIN)
N17454238: C73.1 C74.1 R84.1 U4.1(+VIN)
N17454469: C71.1 C75.1 R85.1 U5.1(+VIN)
N17785545: C134.1 C135.1 R103.2 U13.1(VCC1)
N17785579: C136.1 R104.2 R105.1 U13.2(IN+)
N17785699: C141.1 C142.1 R107.2 U14.1(VCC1)
N17785727: C143.1 R108.2 R110.1 U14.2(IN+)
N17785767: C137.1 C138.1 R106.1 U13.5(VCC2)
N17785926: C144.1 C145.1 R109.1 U14.5(VCC2)
N17788175: C148.1 C149.1 R111.2 U15.1(VCC1)
N17788213: C150.1 R112.2 R114.1 U15.2(IN+)
N17788281: C155.1 C156.1 R115.2 U16.1(VCC1)
N17788301: C157.1 R116.2 R117.1 U16.2(IN+)
N17788345: C151.1 C152.1 R113.1 U15.5(VCC2)
N17788478: C158.1 C159.1 R118.1 U16.5(VCC2)
N17790300: C161.1 C162.1 R119.2 U17.1(VCC1)
N17790352: C163.1 R120.2 R122.1 U17.2(IN+)
N17790406: C167.1 C168.1 R123.2 U18.1(VCC1)
N17790440: C169.1 R124.2 R125.1 U18.2(IN+)
N17790484: C164.1 C165.1 R121.1 U17.5(VCC2)
N17790617: C170.1 C171.1 R126.1 U18.5(VCC2)
N17792648: C173.1 C174.1 R127.2 U19.1(VCC1)
N17792696: C175.1 R128.2 R130.1 U19.2(IN+)
N17792742: C179.1 C180.1 R131.2 U20.1(VCC1)
N17792776: C181.1 R132.2 R133.1 U20.2(IN+)
N17792812: C176.1 C177.1 R129.1 U19.5(VCC2)
N17792937: C182.1 C183.1 R134.1 U20.5(VCC2)
N17820985: R36.2 R43.1
N17820987: R43.2 R48.1
N17935390: R52.2 R56.1
N17935392: R56.2 R65.1
N17935418: R53.2 R57.1
N17935420: R57.2 R66.1
N17935429: R49.2 R53.1
N17935432: R48.2 R52.1
N17962871: C78.1 C79.1 R86.1 U7.1(+VIN)
N17963706: C83.1 C84.1 R87.1 U6.1(+VIN)
N17964909: C115.1 C116.1 R90.1 U10.1(+VIN)
N17965565: C121.1 C122.1 R91.1 U11.1(+VIN)
N17977150: C131.2 R94.1 U12.1(VDD1)
N17977162: C130.1 R92.2 R94.2
N17977230: C132.2 R93.1 U12.16(VDD2)
N17977288: R95.1 U12.2(A1)
N17977296: R97.1 U12.3(A2)
N17977322: R99.1 U12.4(A3)
N17977346: R101.1 U12.5(A4)
N17977366: R96.1 U12.15(B1)
N17977368: R98.1 U12.14(B2)
N17977394: R100.1 U12.13(B3)
N17977396: R102.1 U12.12(B4)
N17988090: CR1.1 CR2.1 L2.3
N17988199: CR3.1 CR4.1 CR5.1 L1.1
N17988317: L1.3 T1.7 T2.7
N17990244: R34.1 R41.2
N17990246: R41.1 R46.2
N17990248: R46.1 R50.2
N17990300: R54.1 R60.2
N17990318: R60.1 R69.2
N17990348: R50.1 R54.2
N17997979: C20.1 C21.1 R38.2 R39.1 R40.1 U1.15(VCC1) U1.16(VCC)
N17998079: R39.2 R45.1 U1.14(VOC)
N18014670: R42.1 R47.2
N18014680: R47.1 R51.2
N18014712: R55.1 R61.2
N18014714: R61.1 R70.2
N18014716: R51.1 R55.2
N18067595: L2.1 T1.4
N18080140: D1.1(A) R2.2
N18080143: D2.1(A) R1.1
N18080178: D7.1(A) R15.2
N18080222: D8.1(A) R14.1
N18096975: CT5.1 D5.3(A) D9.3(A)
N18096977: CT1.1 D3.3(A) D10.3(A)
N18097182: CT8.1 D6.3(A)
N18097184: CT7.1 D4.3(A)
N18126472: T1.1 T2.4
N18143894: CT2.1 D12.3(A)
N18143920: CT6.1 D11.3(A)

Pads without a net: J1 2 4 8 10 12; J3 2 4 6 8 9 10; J5 3 4 7 8; J6 3; NOREF 1; NOREF#7 1; NOREF#8 1; NOREF#9 1; NOREF#11 1; NOREF#12 1; NOREF#14 1; NOREF#15 1; NOREF#17 1; NOREF#19 1; NOREF#21 1; NOREF#22 1; NOREF#26 1; U12 6 7 10 11

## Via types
v1: diameter 0.61, hole 0.305, TOP to BOTTOM, 199 vias

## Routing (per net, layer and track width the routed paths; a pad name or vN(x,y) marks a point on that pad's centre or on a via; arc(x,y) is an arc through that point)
-3V_PSW5: length 16.6
  TOP w0.762: U4.5 57.09,18.18 C139.2 v1(65.07,25.28) 65.61,25.28 U13.8
  BOTTOM w0.762: C137.2 65.96,25.28 v1(65.07,25.28)
-3V_PSW6: length 16.6
  TOP w0.762: U5.5 83.13,18.18 C146.2 v1(91.11,25.28) 91.65,25.28 U14.8
  BOTTOM w0.762: C145.2 92,25.28 v1(91.11,25.28)
-3V_PSW7: length 16.6
  TOP w0.762: U7.5 109.16,18.18 C153.2 v1(117.14,25.28) 117.68,25.28 U15.8
  BOTTOM w0.762: C151.2 118.03,25.28 v1(117.14,25.28)
-3V_PSW8: length 16.6
  TOP w0.762: U16.8 143.72,25.28 v1(143.18,25.28) C160.2 135.2,18.18 U6.5
  BOTTOM w0.762: v1(143.18,25.28) 144.07,25.28 C159.2
-3V_PSW9: length 17.5
  TOP w0.762: U17.8 64.77,160.9 v1(65.79,161.91) C166.2 71.94,161.91 U8.5
  BOTTOM w0.762: v1(65.79,161.91) 65.78,161.93 C164.2
-3V_PSW10: length 17.5
  TOP w0.762: U18.8 90.81,160.9 v1(91.82,161.91) C172.2 97.97,161.91 U9.5
  BOTTOM w0.762: v1(91.82,161.91) 91.81,161.93 C171.2
-3V_PSW11: length 17.5
  TOP w0.762: U19.8 113.67,160.9 v1(114.68,161.91) C178.2 120.83,161.91 U10.5
  BOTTOM w0.762: v1(114.68,161.91) 114.67,161.93 C176.2
-3V_PSW12: length 17.5
  TOP w0.762: U11.5 146.87,161.91 C184.2 140.72,161.91 v1(140.72,161.91) 139.7,160.9 U20.8
  BOTTOM w0.762: v1(140.72,161.91) 140.7,161.93 C183.2
AGND: length 96.1
  TOP w0.381: v1(4.45,150.5) 4.06,150.88 C21.2 C20.2 ; v1(4.7,157.48) 4.06,157.48 3.69,157.1 R45.2
  POWER03 w0.381: v1(4.45,150.5) 4.45,117.09 8.76,112.78 8.76,102.74 23.24,88.27 v1(24.13,88.27)
  BOTTOM w0.381: v1(35.56,82.55) C130.2 34.29,82.67 C131.1 ; C52.1 C53.1 14.88,60.69 v1(14.61,60.96) ; v1(4.45,160.27) 5.21,159.51 5.21,157.99 v1(4.7,157.48) 4.7,150.75 v1(4.45,150.5) ; U12.8 v1(24.13,88.27)
  vias: v1(13.34,1.91) v1(18.41,1.91) v1(22.86,71.37) v1(22.86,70.23) v1(22.86,68.96) v1(22.86,67.56) v1(22.86,66.29) v1(22.86,65.15) v1(23.5,1.91) v1(24.26,71.37) v1(24.26,70.23) v1(24.26,68.96) v1(24.26,67.56) v1(24.26,66.29) v1(24.26,65.15) v1(25.53,71.37) v1(25.53,70.23) v1(25.53,68.96) v1(25.53,67.56) v1(25.53,66.29) v1(25.53,65.15) v1(26.92,71.37) v1(26.92,70.23) v1(26.92,68.96) v1(26.92,67.56) v1(26.92,66.29) v1(26.92,65.15) v1(28.19,71.37) v1(28.19,70.23) v1(28.19,68.96) v1(28.19,67.56) v1(28.19,66.29) v1(28.19,65.15) v1(28.57,1.91) v1(33.66,67.94) v1(33.66,1.91) v1(38.73,1.91) v1(43.81,1.91) v1(48.9,1.91) v1(53.98,1.91) v1(55.93,12.06) v1(57.84,12.06) v1(59.05,1.91) v1(59.74,12.06) v1(64.14,1.91) v1(69.22,1.91) v1(71.12,11.07) v1(74.3,1.91) v1(79.38,1.91) v1(81.97,12.06) v1(83.87,12.06) v1(84.45,1.91) v1(85.78,12.06) v1(89.53,1.91) v1(94.61,1.91) v1(97.26,11.07) v1(99.69,1.91) v1(104.78,1.91) v1(108,12.06) v1(109.91,12.06) v1(109.86,1.91) v1(111.81,12.06) v1(114.94,1.91) v1(120.02,1.91) v1(123.19,11.07) v1(125.09,1.91) v1(130.18,1.91) v1(134.04,12.06) v1(135.25,1.91) v1(135.94,12.06) v1(137.85,12.06) v1(140.34,1.91) v1(145.41,1.91) v1(149.22,11.07) v1(150.5,1.91)
P6.5V: length 31.3
  POWER03 w0.762: J5.10 15.96,83.19 18.54,83.19 29.21,72.52 v1(29.21,62.23) v1(29.21,60.96)
PGND: length 3
  GND02 w1.016: C633.2 30.48,59.94
SGND: length 4.6
  BOTTOM w0.381: v1(33.02,107.31) 33.02,106.17 C129.2 33.02,105.92 C132.1 ; U12.9 v1(24.13,100.97)
  vias: v1(53.47,167.64) v1(53.47,166.37) v1(59.69,173.72) v1(71.12,172.72) v1(73.03,172.72) v1(74.93,172.72) v1(85.72,173.72) v1(97.16,172.72) v1(99.06,172.72) v1(100.97,172.72) v1(108.58,173.72) v1(120.02,172.72) v1(121.92,172.72) v1(123.83,172.72) v1(134.62,173.72) v1(146.05,172.72) v1(147.96,172.72) v1(149.86,172.72)
CAN5V_GND: length 16.4
  TOP w0.381: J6.2 13.34,105.28 13.34,107.82 8.76,112.39 J3.11
CAN_5V: length 20.8
  TOP w0.381: J6.1 12.45,103.63 12.45,107.44 8.69,111.2 5.13,111.2 4.06,112.27 J3.12
CLAMPQA: length 20.8
  TOP w0.762: U13.7 67.36,28.07 68,28.7 Q1.4 68.31,31.25 R4.1 71.81,33.47 R2.1
  BOTTOM w0.762: C5.1 67.49,30.42 Q1.4 68.06,30.99 R8.2
CLAMPQB: length 20.6
  TOP w0.762: U14.7 93.4,28.07 94.03,28.7 Q3.4 94.35,31.25 R19.1 97.84,33.22 R15.1
  BOTTOM w0.762: C14.1 93.52,30.42 Q3.4 94.09,30.99 R21.2
CLAMPQC: length 20.8
  TOP w0.762: U15.7 119.43,28.07 120.07,28.7 Q2.4 120.38,31.25 R5.2 123.88,33.47 R1.2
  BOTTOM w0.762: R9.2 120.13,30.99 Q2.4 119.56,30.42 C4.1
CLAMPQD: length 21.2
  TOP w0.762: R14.2 150.36,32.01 150.55,31.83 R20.2 148.84,30.61 148.52,30.93 Q4.4 146.1,28.7 145.47,28.07 U16.7
  BOTTOM w0.762: R22.2 146.16,30.99 Q4.4 146.23,30.81 C15.1
CLAMPQSA: length 18.3
  TOP w0.762: R58.1 62.55,153.54 Q7.4 62.87,156.08 63.5,156.72 U17.7
  BOTTOM w0.762: R62.2 62.8,153.79 Q7.4 63.38,154.37 C22.1
CLAMPQSB: length 18.3
  TOP w0.762: U18.7 89.53,156.72 88.9,156.08 Q17.4 88.58,153.54 R72.1
  BOTTOM w0.762: R75.2 88.84,153.79 Q17.4 89.41,154.37 C42.1
CLAMPQSC: length 18.3
  TOP w0.762: R59.2 111.44,153.54 Q16.4 111.76,156.08 112.39,156.72 U19.7
  BOTTOM w0.762: C23.1 112.27,154.37 Q16.4 111.7,153.79 R64.2
CLAMPQSD: length 18.4
  TOP w0.762: U20.7 138.43,156.72 137.79,156.08 Q18.4 137.48,153.54 R73.2
  BOTTOM w0.762: C43.1 138.31,154.37 Q18.4 137.55,153.61 R76.2
CS: length 77.8
  TOP w0.635: v1(58.42,82.55) 58.74,82.87 D4.2 D12.2 ; D11.2 D6.2 58.73,79.06 v1(58.42,79.38) 28.57,79.38 21.97,85.98 12.06,85.98 10.03,83.95 10.03,78.99 6.6,75.56
  BOTTOM w0.381: v1(58.42,79.38) 57.66,80.14 57.66,81.79 v1(58.42,82.55)
CS_PRI: length 119.7
  TOP w0.635: v1(58.42,70.48) 58.73,70.17 D5.2 D9.2 ; J1.18 8.38,35.43 8.38,69.34 11.3,72.26 11.3,83.19 12.7,84.58 21.21,84.58 32.13,73.66 v1(58.42,73.66) 58.74,73.98 D3.2 D10.2
  BOTTOM w0.381: v1(58.42,73.66) 57.66,72.9 57.66,71.25 v1(58.42,70.48)
CS_RTN: length 76.7
  TOP w0.635: J2.3 8.64,80.14 8.64,84.58 11.3,87.25 23.11,87.25 29.08,81.28 v1(58.42,81.28) 58.74,80.96 D6.1 D11.1 ; D12.1 D4.1 58.73,84.77 v1(58.42,84.45)
  BOTTOM w0.381: v1(58.42,84.45) 59.18,83.69 59.18,82.04 v1(58.42,81.28)
CS_RTN_PRI: length 120.6
  TOP w0.635: J1.20 9.78,34.29 9.78,68.45 12.83,71.5 12.83,82.68 13.46,83.31 19.94,83.31 30.86,72.39 v1(58.42,72.39) 58.74,72.07 D5.1 D9.1 ; v1(58.42,75.56) 58.73,75.88 D3.1 D10.1
  BOTTOM w0.381: v1(58.42,75.56) 59.31,74.68 59.31,73.28 v1(58.42,72.39)
DC-OV: length 35.8
  BOTTOM w0.152: J1.22 13.47,35.44 13.47,53.09 16.38,56.01 19.3,56.01 19.68,55.63 R70.1
DC_14V_INPUT: length 68
  TOP w1.016: J5.1 19.53,69.01 C55.1 19.53,54.58 13.08,48.13 13.08,23.88 7.62,18.42 7.62,14.22 J4.2
DC_FB: length 33.7
  BOTTOM w0.152: R69.1 16.01,54.74 14.1,52.83 14.1,33.53 J1.24
DCINPUT: length 6.9
  BOTTOM w0.152: 19.81,19.68 19.82,19.69
  BOTTOM w0.508: R42.2 19.68,24.26 R34.2 19.82,19.69
DCPWM1A_1H: length 137.7
  TOP w0.508: R104.1 v1(67.31,9.16)
  POWER03 w0.152: v1(67.31,9.16) 67.31,7.37 65.28,5.33 16.83,5.33 12.7,9.47 12.7,38.23 19.18,44.7 19.18,59.82 5.33,73.66 5.33,76.83 J2.4
DCPWM1A_1L: length 161.7
  TOP w0.508: R108.1 v1(93.45,9.16)
  POWER03 w0.152: 4.06,75.56 4.06,74.04 18.54,59.56 18.54,45.09 12.06,38.61 12.06,9.29 16.51,4.85 90.07,4.85 93.45,8.23 v1(93.45,9.16)
DCPWM2A_2H: length 200.9
  TOP w0.508: R112.1 v1(119.38,9.16)
  POWER03 w0.152: J2.7 7.75,82.04 7.75,80.14 7.11,79.5 3.56,79.5 2.98,78.93 2.98,74.36 17.78,59.56 17.78,45.34 11.43,38.99 11.43,9.14 16.26,4.32 115.32,4.32 119.38,8.38 v1(119.38,9.16)
DCPWM2A_2L: length 226.2
  TOP w0.508: R116.1 v1(145.41,9.16)
  POWER03 w0.152: v1(145.41,9.16) 145.41,8.26 140.97,3.81 16.13,3.81 10.92,9.02 10.92,39.62 17.02,45.72 17.02,59.56 2.57,74.02 2.57,81.31 3.17,81.92 5.33,81.92 6.6,80.64
DRVA: length 8.4
  TOP w0.762: D1.2 72.91,28.44 R4.2 69.52,28.44 68.63,27.56 U13.6
DRVA_G: length 42.3
  TOP w0.762: U4.6 56.66,20.72 62.74,26.79 C139.1 64.19,28.32 65.46,29.59 Q1.3
  POWER03 w0.762: v1(72.06,25.65) 72.06,26.37 71.25,27.18 67.56,27.18 65.46,29.29 Q1.3
  BOTTOM w0.762: C5.2 65.97,30.42 Q1.3 65.46,32.44 66.55,33.53 71.37,33.53 R8.1 ; v1(72.06,25.65) 72.13,25.58 C138.2
DRVB: length 8.2
  TOP w0.762: U14.6 94.67,27.1 96.01,28.44 R19.2 99.23,27.06 D7.2
DRVB_G: length 42.4
  TOP w0.762: Q3.3 91.49,29.59 90.22,28.32 C146.1 88.77,26.79 82.7,20.72 U5.6
  POWER03 w0.762: v1(98.09,25.65) 98.09,26.37 97.28,27.18 93.49,27.18 91.49,29.18 Q3.3
  BOTTOM w0.762: C14.2 92,30.42 Q3.3 91.49,32.44 92.58,33.53 97.51,33.53 R21.1 ; v1(98.09,25.65) 98.17,25.58 C144.2
DRVC: length 8.4
  TOP w0.762: D2.2 124.98,28.44 R5.1 121.59,28.44 120.7,27.56 U15.6
DRVC_G: length 42.3
  TOP w0.762: Q2.3 117.53,29.59 116.26,28.32 C153.1 114.81,26.79 108.73,20.72 U7.6
  POWER03 w0.762: Q2.3 117.53,29.29 119.63,27.18 123.37,27.18 124.13,26.42 v1(124.13,25.65)
  BOTTOM w0.762: v1(124.13,25.65) 124.2,25.58 C152.2 ; C4.2 118.04,30.42 Q2.3 117.53,32.44 118.62,33.53 123.44,33.53 R9.1
DRVD: length 8.5
  TOP w0.762: D8.2 151.93,26.42 R20.1 147.5,27.81 146.74,27.05 U16.6
DRVD_G: length 42.4
  TOP w0.762: U6.6 134.77,20.72 140.84,26.79 C160.1 142.29,28.32 143.56,29.59 Q4.3
  POWER03 w0.762: Q4.3 143.56,29.29 145.67,27.18 149.22,27.18 150.16,26.24 v1(150.16,25.65)
  BOTTOM w0.762: v1(150.16,25.65) 150.24,25.58 C158.2 ; C15.2 144.71,28.52 143.56,29.67 Q4.3 143.56,32.44 144.65,33.53 149.48,33.53 R22.1
DRVSA: length 5.3
  TOP w0.762: U17.6 62.23,157.23 61.34,156.34 R58.2
DRVSB: length 5.3
  TOP w0.762: U18.6 88.27,157.23 87.38,156.34 R72.2
DRVSC: length 5.3
  TOP w0.762: U19.6 111.12,157.23 110.24,156.34 R59.1
DRVSD: length 5.3
  TOP w0.762: U20.6 137.16,157.23 136.27,156.34 R73.1
IGND: length 61.2
  TOP w1.016: J5.2 16.03,69.97 C55.2 16.03,54.13 11.18,49.28 11.18,24.89 4.26,17.98 J4.1
IOUT_ADC: length 130
  TOP w0.381: v1(3.17,158.75) 3.94,159.51 4.95,159.51 6.58,157.88 U1.12
  POWER03 w0.152: v1(3.17,158.75) 2.03,157.61 2.03,81.92 1.75,81.64 1.75,72.92 2.16,72.52 2.16,41.15 3.43,39.88 5.46,39.88 J1.14
OUTPUT_OC: length 138.6
  TOP w0.381: U1.13 6.71,156.61 4.57,158.75 v1(4.45,158.75) 3.7,158 2.43,158 1.91,157.48 1.91,156.72 R40.2
  POWER03 w0.152: J1.16 5.33,37.47 2.67,37.47 1.4,38.73 1.4,157.99 2.79,159.38 3.81,159.38 v1(4.45,158.75)
SPGND: length 7.9
  GND02 w0.152: 13.27,119.44 C40.2 13.34,119.38
  GND02 w1.016: 10.79,116.97 13.27,119.44
  BOTTOM w0.508: 29.15,119.38 R79.2
SR-PWM-A: length 28.7
  POWER03 w0.152: 6.6,85.72 6.86,85.98 20.32,85.98 24.13,82.17 30.1,82.17 v1(31.75,83.82)
  BOTTOM w0.152: R95.2 v1(31.75,83.82)
SR-PWM-A-S: length 141.5
  TOP w0.152: R120.1 62.41,175.62
  TOP w0.508: 62.41,175.62 v1(63.55,175.62)
  POWER03 w0.152: v1(63.55,175.62) 62.64,174.71 59.65,174.71 58.78,175.59 13.28,175.59 8.76,171.07 8.76,116.97 v1(12.06,113.67)
  BOTTOM w0.152: R96.2 31.75,105.16 24.26,112.65 13.72,112.65 12.7,113.67 v1(12.06,113.67)
SR-PWM-B: length 30.2
  POWER03 w0.152: 4.06,85.72 5.14,86.8 20.76,86.8 24.89,82.68 29.34,82.68 v1(30.48,83.82)
  BOTTOM w0.152: R97.2 v1(30.48,83.82)
SR-PWM-B-S: length 168.9
  TOP w0.508: R124.1 v1(89.59,175.62)
  POWER03 w0.152: v1(10.79,113.67) 8.13,116.33 8.13,171.58 13.08,176.53 64.64,176.53 65.66,175.51 82.55,175.51 83.44,176.4 88.81,176.4 v1(89.59,175.62)
  BOTTOM w0.152: v1(10.79,113.67) 11.43,113.03 12.45,113.03 13.34,112.14 23.5,112.14 30.48,105.16 R98.2
SR-PWM-C: length 26.1
  POWER03 w0.152: v1(29.21,83.82) 28.57,83.19 25.65,83.19 20.57,88.27 J2.11
  BOTTOM w0.152: R99.2 v1(29.21,83.82)
SR-PWM-C-S: length 195.2
  TOP w0.508: R128.1 v1(112.45,175.62)
  POWER03 w0.152: v1(112.45,175.62) 111.41,176.66 107.19,176.66 105.92,175.39 100.46,175.39 99.7,176.15 91.57,176.15 89.79,177.93 70.36,177.93 68.58,176.15 65.66,176.15 64.01,177.8 13.34,177.8 7.49,171.96 7.49,115.7 10.16,113.03 11.43,113.03 v1(12.06,112.39)
  BOTTOM w0.152: R100.2 29.21,105.03 22.73,111.51 12.95,111.51 v1(12.06,112.39)
SR-PWM-D: length 27.9
  POWER03 w0.152: J2.12 5.33,89.53 20.83,89.53 26.54,83.82 v1(27.94,83.82)
  BOTTOM w0.152: R101.2 v1(27.94,83.82)
SR-PWM-D-S: length 220.4
  TOP w0.508: R132.1 v1(138.48,175.62)
  POWER03 w0.152: v1(10.79,112.39) 10.79,112.39 9.91,112.39 6.86,115.44 6.86,172.59 12.7,178.44 115.82,178.44 118.64,175.62 131.94,175.62 132.72,176.4 137.7,176.4 v1(138.48,175.62)
  BOTTOM w0.152: v1(10.79,112.39) 12.32,110.87 22.1,110.87 27.94,105.03 R102.2
SRA_G: length 44.2
  TOP w0.762: Q7.3 65.41,155.19 66.67,156.46 C166.1 72.96,160.39 U8.6
  POWER03 w0.762: v1(58.8,159.13) 58.8,158.62 59.56,157.86 64.14,157.86 65.41,156.59 Q7.3
  BOTTOM w0.762: v1(58.8,159.13) 58.73,159.21 C165.2 ; R62.1 59.44,151.26 64.31,151.26 65.41,152.35 Q7.3 64.89,154.37 C22.2
SRB_G: length 43.7
  TOP w0.762: Q17.3 91.44,156.72 92.71,157.99 C172.1 98.99,160.39 U9.6
  POWER03 w0.762: Q17.3 91.44,155.5 89.33,157.61 85.6,157.61 84.84,158.37 v1(84.84,159.13)
  BOTTOM w0.762: v1(84.84,159.13) 84.76,159.21 C170.2 ; C42.2 90.93,154.37 Q17.3 91.44,152.35 90.35,151.26 85.47,151.26 R75.1
SRC_G: length 43.7
  TOP w0.762: U10.6 121.85,160.39 C178.1 115.57,156.46 114.3,155.19 Q16.3
  POWER03 w0.762: v1(107.7,159.13) 107.7,158.37 108.46,157.61 112.19,157.61 114.3,155.5 Q16.3
  BOTTOM w0.762: C177.2 107.62,159.21 v1(107.7,159.13) ; C23.2 113.79,154.37 Q16.3 114.3,152.35 113.21,151.26 108.33,151.26 R64.1
SRD_G: length 44.1
  TOP w0.762: Q18.3 140.34,156.72 141.6,157.99 C184.1 147.89,160.39 U11.6
  POWER03 w0.508: v1(133.73,159.13) 135.13,157.73 139.32,157.73 140.34,156.72 Q18.3
  BOTTOM w0.762: v1(133.73,159.13) 133.66,159.21 C182.2 ; C43.2 139.82,154.37 Q18.3 140.34,152.15 139.45,151.26 134.18,151.26 R76.1
VO1+: length 18.6
  BOTTOM w0.381: J3.1 5.36,100.94 5.36,116.35 R65.2
VO2+: length 16.1
  BOTTOM w0.381: J3.3 8,103.63 8,116.46 R66.2
VO+: length 9.1
  BOTTOM w0.508: R36.1 R37.1 11.24,145.55 ; 29.15,145.41 R63.1
VP3.3D: length 106.5
  TOP w0.381: v1(3.17,150.5) 2.54,151.13 R38.1
  POWER03 w0.152: v1(3.17,150.5) 2.54,149.86 2.54,81.85 2.16,81.47 2.16,73.28 2.79,72.64 2.79,50.67 3.3,50.16 5.33,50.16 J1.6
VP+5V: length 209.6
  TOP w0.508: v1(66.29,9.14) 65.66,9.14 64.77,10.03 R103.1 ; R111.1 116.84,10.03 117.73,9.14 v1(118.36,9.14) ; v1(92.43,9.14) 91.8,9.14 90.91,10.03 R107.1 ; v1(144.4,9.14) 143.76,9.14 142.88,10.03 R115.1
  POWER03 w0.508: v1(66.29,9.14) 66.29,9.91 70.36,13.97 85.85,13.97 90.68,9.14 v1(92.43,9.14) 92.43,9.5 96.9,13.97 111.76,13.97 116.59,9.14 v1(118.36,9.14) 118.36,9.53 122.81,13.97 139.57,13.97 v1(144.4,9.14)
  BOTTOM w0.381: R92.1 27.43,82.55 20.83,75.95 20.83,58.55
  BOTTOM w0.508: J1.23 9.53,20.57 9.53,13.34 16.38,6.48 51.31,6.48 52.58,5.21 65.15,5.21 66.29,6.35 v1(66.29,9.14)
VP+15V: length 124.9
  POWER03 w1.016: v1(64.82,6.99) 64.19,6.35 17.91,6.35 14.1,10.16 14.1,36.32 21.72,43.94 21.72,73.28 18.39,76.61 J5.5
  vias: v1(64.82,8.26) v1(90.86,8.26) v1(90.86,6.99) v1(116.89,8.26) v1(116.89,6.99) v1(142.93,8.26) v1(142.93,6.99)
VS+5V: length 234.9
  TOP w0.381: v1(90.68,175.62) 92.08,174.23 R123.1 ; v1(139.57,175.62) 140.97,174.23 R131.1 ; R127.1 114.94,174.23 v1(113.54,175.62) ; R119.1 66.04,174.23 v1(64.64,175.62)
  TOP w0.508: J3.7 v1(11.43,107.31)
  POWER03 w0.508: v1(139.57,175.62) 139.57,174.75 136.02,171.2 120.02,171.2 115.59,175.62 v1(113.54,175.62) 113.54,175.39 108.97,170.81 95.49,170.81 v1(90.68,175.62) 90.68,175.26 86.23,170.81 68.71,170.81 64.64,174.88 v1(64.64,175.62) ; v1(47.12,167.64) 54.8,159.96 54.8,151.19 59.82,146.18 59.82,125.86 44.58,110.62 v1(34.41,110.62) 14.73,110.62 v1(11.43,107.31)
  BOTTOM w0.381: R93.2 34.29,105.92 C129.1 v1(34.41,110.62)
  BOTTOM w0.508: v1(64.64,175.62) 64.64,176.02 63.75,176.91 58.04,176.91 53.09,171.96 49.53,171.96 v1(47.12,169.54) v1(47.12,167.64)
VS+15V: length 100.1
  POWER03 w1.016: J6.4 19.22,108.9 44.89,108.9 61.21,125.22 61.21,146.56 56.01,151.76 56.01,170.56 v1(56.52,171.07)
  vias: v1(66.04,177.8) v1(66.04,176.78) v1(92.08,177.8) v1(92.08,176.78) v1(114.94,177.8) v1(114.94,176.78) v1(140.97,177.8) v1(140.97,176.78)
N16148248: length 2.5
  BOTTOM w0.381: R63.2 21.96,145.55 R67.1
N16148534: length 2.5
  BOTTOM w0.381: R68.2 21.96,137.66 R71.1
N16148538: length 2.3
  BOTTOM w0.381: R67.2 R68.1
N16148540: length 2.5
  BOTTOM w0.381: R74.2 21.96,127.13 R77.1
N16148544: length 2.5
  BOTTOM w0.381: R79.1 21.96,119.25 R78.2
N16148550: length 13.8
  BOTTOM w0.381: C25.2 31.69,137.79 R71.2 ; R74.1 31.69,127 C39.1
N16320789: length 2.3
  BOTTOM w0.381: R77.2 R78.1
N17266948: length 2.3
  BOTTOM w0.381: R37.2 R44.1
N17266951: length 2.3
  BOTTOM w0.381: R44.2 R49.1
N17785545: length 5.3
  TOP w0.508: U13.1 66.09,12.51 C135.1 ; R103.2 C135.1 ; C135.1 C134.1
N17785579: length 10.8
  TOP w0.508: v1(71.12,12.34) 71,12.46 R105.1 C136.1 68.58,13.08 67.36,14.3 U13.2 ; R104.2 v1(71.12,9.16)
  BOTTOM w0.508: v1(71.12,12.34) 70.23,11.45 70.23,10.05 v1(71.12,9.16)
N17785699: length 5.3
  TOP w0.508: C141.1 92.13,12.52 U14.1 ; C141.1 R107.2 ; C141.1 C142.1
N17785727: length 10.6
  TOP w0.508: v1(97.16,12.34) 97.03,12.46 R110.1 C143.1 94.61,12.57 94.61,13.08 93.4,14.3 U14.2 ; R108.2 v1(97.16,9.16)
  BOTTOM w0.508: v1(97.16,9.16) 96.39,9.92 96.39,11.57 v1(97.16,12.34)
N17785767: length 0.9
  TOP w0.508: v1(70.79,25.65) 70.69,25.76 U13.5
N17785926: length 0.9
  TOP w0.508: v1(96.82,25.65) 96.72,25.76 U14.5
N17788175: length 5.3
  TOP w0.508: C149.1 C148.1 ; C149.1 118.16,12.51 U15.1 ; C149.1 R111.2
N17788213: length 10.8
  TOP w0.508: v1(123.19,12.34) 123.07,12.46 R114.1 C150.1 120.65,12.95 119.43,14.17 U15.2 ; R112.2 v1(123.19,9.16)
  BOTTOM w0.508: v1(123.19,12.34) 122.3,11.45 122.3,10.05 v1(123.19,9.16)
N17788281: length 5.3
  TOP w0.508: C156.1 C155.1 ; C156.1 R115.2 ; C156.1 144.2,12.51 U16.1
N17788301: length 10.8
  TOP w0.508: v1(149.22,12.34) 149.1,12.46 R117.1 C157.1 146.69,13.08 145.47,14.3 U16.2 ; R116.2 v1(149.22,9.16)
  BOTTOM w0.508: v1(149.22,9.16) 148.34,10.05 148.34,11.45 v1(149.22,12.34)
N17788345: length 0.9
  TOP w0.508: U15.5 122.76,25.76 v1(122.86,25.65)
N17788478: length 0.9
  TOP w0.508: U16.5 148.79,25.76 v1(148.89,25.65)
N17790300: length 5.2
  TOP w0.508: U17.1 C162.1 ; C162.1 R119.2 ; C162.1 C161.1
N17790352: length 10.7
  TOP w0.508: U17.2 63.5,170.67 62.23,171.94 C163.1 R122.1 59.87,172.32 v1(59.74,172.45) ; R120.2 v1(59.74,175.62)
  BOTTOM w0.508: v1(59.74,172.45) 60.58,173.29 60.58,174.79 v1(59.74,175.62)
N17790406: length 5.2
  TOP w0.508: R123.2 C167.1 ; C167.1 U18.1 ; C167.1 C168.1
N17790440: length 10.7
  TOP w0.508: v1(85.78,172.45) 85.9,172.32 R125.1 C169.1 88.27,171.94 89.53,170.67 U18.2 ; R124.2 v1(85.78,175.62)
  BOTTOM w0.508: v1(85.78,172.45) 86.61,173.29 86.61,174.79 v1(85.78,175.62)
N17790484: length 0.9
  TOP w0.508: v1(60.07,159.13) 60.17,159.03 U17.5
N17790617: length 0.9
  TOP w0.508: U18.5 86.21,159.03 v1(86.11,159.13)
N17792648: length 5.2
  TOP w0.508: C173.1 U19.1 ; C173.1 R127.2 ; C173.1 C174.1
N17792696: length 10.7
  TOP w0.508: U19.2 112.39,170.67 111.12,171.94 C175.1 R130.1 108.76,172.32 v1(108.64,172.45) ; R128.2 v1(108.64,175.62)
  BOTTOM w0.508: v1(108.64,175.62) 109.47,174.79 109.47,173.29 v1(108.64,172.45)
